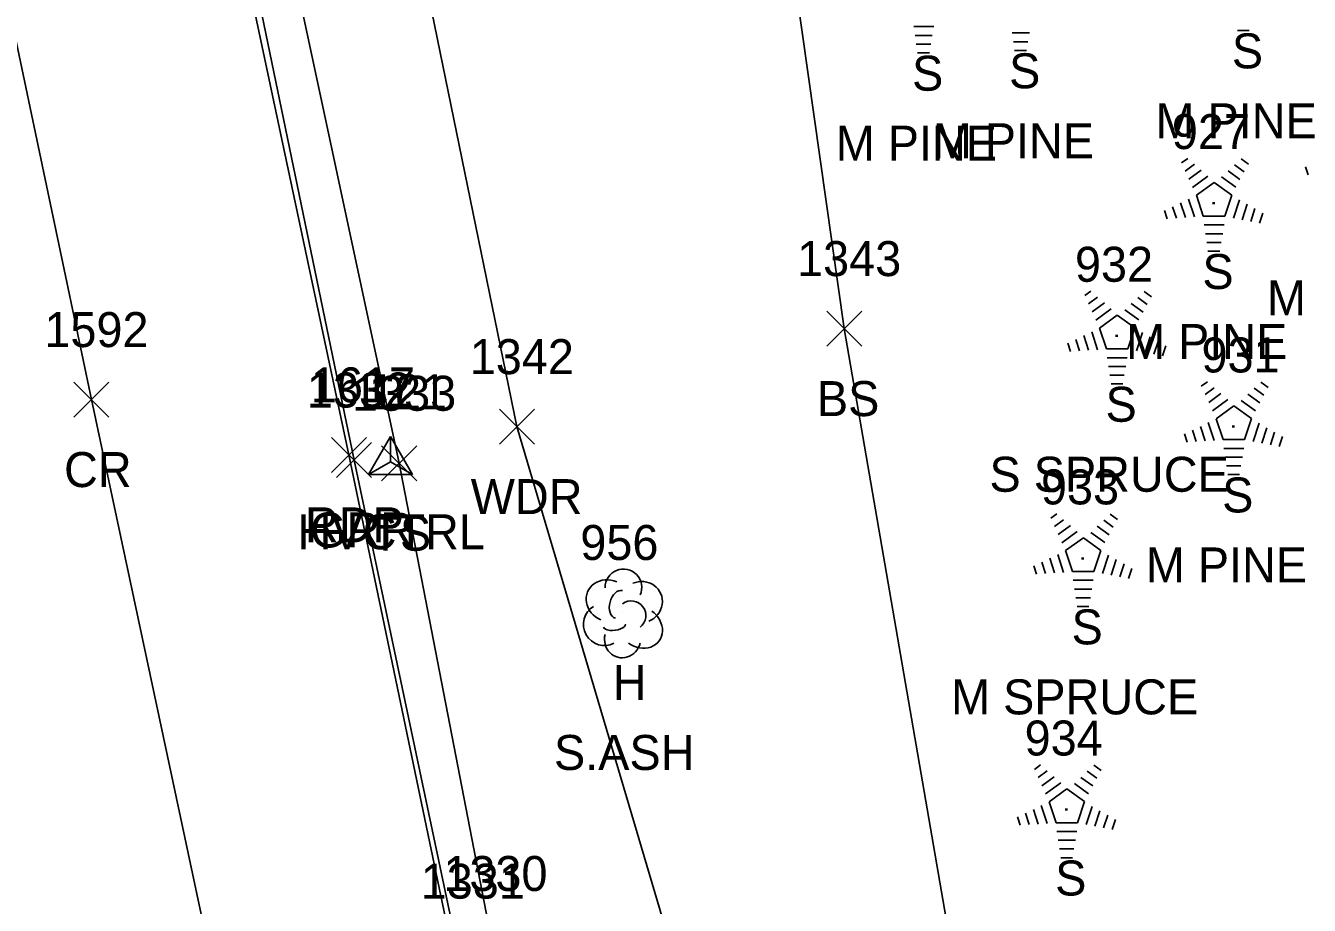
# Model space of a CAD drawing. Extents: x 1545627 to 1546562, y 571176 to 576667.
# Drawn here: x 1546058 to 1546131.4, y 572393.7 to 572443.9 of the extents above; entities that cross this region are included whole.
import ezdxf

# ---------------------------------------------------------------- set-up
doc = ezdxf.new("R2010")
doc.units = 0
for name, color, linetype in [('C_A', 7, 'Continuous'), ('C_I', 7, 'Continuous'), ('CPSM', 7, 'Continuous'), ('L_A', 7, 'Continuous'), ('L_C', 7, 'Continuous'), ('L_I', 7, 'Continuous'), ('L_TIC', 7, 'Continuous'), ('LAWA', 7, 'Continuous'), ('LELB', 7, 'Continuous'), ('LTC', 7, 'Continuous'), ('LTD', 7, 'Continuous'), ('P_A', 7, 'Continuous'), ('P_I', 7, 'Continuous'), ('P_TIC', 7, 'Continuous'), ('PET', 7, 'Continuous'), ('PRC', 7, 'Continuous'), ('R_A', 7, 'Continuous'), ('R_I', 7, 'Continuous'), ('R_TIC', 7, 'Continuous'), ('RGR', 7, 'Continuous')]:
    doc.layers.add(name, color=color, linetype=linetype)

msp = doc.modelspace()

# ---------------------------------------------------------------- linework, layer by layer
at = {"layer": 'CPSM'}
for p, q in [((1546077.639, 572418.298), (1546078.889, 572420.463)), ((1546080.139, 572418.298), (1546078.889, 572420.463)), ((1546078.89, 572419.019), (1546078.889, 572420.463)), ((1546077.639, 572418.298), (1546078.89, 572419.019)), ((1546078.89, 572419.019), (1546078.89, 572419.019)), ((1546078.89, 572419.019), (1546080.139, 572418.298)), ((1546077.639, 572418.298), (1546080.139, 572418.298))]:
    msp.add_line(p, q, dxfattribs=at)
at = {"layer": 'L_TIC'}
for points in [[(1546103.81, 572425.631), (1546105.81, 572427.631)], [(1546105.81, 572425.631), (1546103.81, 572427.631)], [(1546085.111, 572420.028), (1546087.111, 572422.028)], [(1546087.111, 572420.028), (1546085.111, 572422.028)], [(1546078.385, 572417.936), (1546080.385, 572419.936)], [(1546080.385, 572417.936), (1546078.385, 572419.936)]]:
    msp.add_lwpolyline(points, dxfattribs=at)
at = {"layer": 'LAWA'}
msp.add_lwpolyline([(1546132.696, 572194.892), (1546123.453, 572251.154), (1546111.937, 572304.897), (1546099.961, 572374.277), (1546086.111, 572421.028), (1546079.849, 572451.625), (1546071.905, 572496.172), (1546064.394, 572527.582), (1546058.594, 572548.653), (1546052.091, 572585.928), (1546038.425, 572619.665), (1546027.83, 572654.921), (1546018.77, 572685.669), (1546005.342, 572728.46), (1545993.814, 572765.207), (1545980.931, 572799.992)], dxfattribs=at)
at = {"layer": 'LELB'}
for points in [[(1546125.533, 572192.436), (1546119.789, 572223.125), (1546112.539, 572267.479), (1546101.484, 572308.512), (1546092.302, 572354.824), (1546084.689, 572391.492), (1546079.385, 572418.936), (1546072.143, 572452.753), (1546063.265, 572495.373), (1546056.178, 572525.93), (1546052.452, 572548.057), (1546043.75, 572580.7), (1546033.096, 572617.265), (1546022.592, 572652.847), (1546012.21, 572685.195), (1545999.024, 572724.088), (1545985.45, 572763.438), (1545973.138, 572794.948)], [(1546138.092, 572206.647), (1546133.659, 572247.148), (1546122.485, 572312.188), (1546113.316, 572377.356), (1546104.81, 572426.631), (1546099.996, 572460.654), (1546092.988, 572497.654), (1546081.836, 572529.538), (1546071.729, 572550.604), (1546058.937, 572584.302), (1546058.009, 572591.614), (1546041.849, 572621.011), (1546036.285, 572644.955)]]:
    msp.add_lwpolyline(points, dxfattribs=at)
at = {"layer": 'LTC'}
for p, q in [((1546109.929, 572443.89), (1546108.784, 572443.89)), ((1546109.845, 572443.39), (1546108.857, 572443.39)), ((1546115.389, 572443.526), (1546114.401, 572443.526)), ((1546127.949, 572443.667), (1546127.274, 572443.667)), ((1546109.761, 572442.89), (1546108.93, 572442.89)), ((1546115.305, 572443.026), (1546114.474, 572443.026)), ((1546115.222, 572442.526), (1546114.547, 572442.526)), ((1546109.678, 572442.39), (1546109.003, 572442.39)), ((1546124.086, 572436.101), (1546124.44, 572436.358)), ((1546124.295, 572435.635), (1546124.824, 572436.02)), ((1546127.113, 572435.993), (1546127.662, 572435.594)), ((1546127.484, 572436.341), (1546127.903, 572436.037)), ((1546124.505, 572435.17), (1546125.208, 572435.681)), ((1546124.714, 572434.704), (1546125.593, 572435.342)), ((1546126.371, 572435.296), (1546127.18, 572434.708)), ((1546126.742, 572435.645), (1546127.421, 572435.151)), ((1546131.166, 572435.883), (1546131.319, 572435.415)), ((1546124.939, 572434.249), (1546125.951, 572434.983)), ((1546125.951, 572434.983), (1546126.948, 572434.258)), ((1546124.029, 572433.813), (1546124.3, 572432.978)), ((1546124.484, 572434.03), (1546124.815, 572433.01)), ((1546124.939, 572434.249), (1546125.326, 572433.055)), ((1546126.948, 572434.258), (1546126.556, 572433.055)), ((1546127.385, 572433.988), (1546127.047, 572432.948)), ((1546127.83, 572433.737), (1546127.542, 572432.853)), ((1546123.118, 572433.38), (1546123.27, 572432.912)), ((1546123.573, 572433.597), (1546123.785, 572432.945)), ((1546126.556, 572433.055), (1546125.326, 572433.055)), ((1546128.274, 572433.487), (1546128.037, 572432.758)), ((1546128.718, 572433.237), (1546128.532, 572432.663)), ((1546126.518, 572432.555), (1546125.373, 572432.555)), ((1546126.434, 572432.055), (1546125.446, 572432.055)), ((1546126.351, 572431.555), (1546125.519, 572431.555)), ((1546126.267, 572431.055), (1546125.592, 572431.055)), ((1546118.549, 572428.516), (1546118.904, 572428.773)), ((1546121.948, 572428.756), (1546122.367, 572428.452)), ((1546118.759, 572428.05), (1546119.288, 572428.435)), ((1546118.968, 572427.585), (1546119.672, 572428.096)), ((1546121.206, 572428.06), (1546121.885, 572427.566)), ((1546121.576, 572428.408), (1546122.126, 572428.009)), ((1546119.178, 572427.119), (1546120.056, 572427.757)), ((1546119.403, 572426.664), (1546120.414, 572427.398)), ((1546120.414, 572427.398), (1546121.411, 572426.673)), ((1546120.834, 572427.711), (1546121.644, 572427.123)), ((1546118.948, 572426.445), (1546119.279, 572425.425)), ((1546119.403, 572426.664), (1546119.79, 572425.47)), ((1546121.411, 572426.673), (1546121.02, 572425.47)), ((1546121.849, 572426.403), (1546121.511, 572425.363)), ((1546117.582, 572425.795), (1546117.734, 572425.327)), ((1546118.037, 572426.012), (1546118.249, 572425.36)), ((1546118.493, 572426.228), (1546118.764, 572425.393)), ((1546122.293, 572426.152), (1546122.006, 572425.268)), ((1546122.738, 572425.902), (1546122.501, 572425.173)), ((1546121.02, 572425.47), (1546119.79, 572425.47)), ((1546120.982, 572424.97), (1546119.837, 572424.97)), ((1546123.182, 572425.652), (1546122.996, 572425.078)), ((1546120.898, 572424.47), (1546119.91, 572424.47)), ((1546120.814, 572423.97), (1546119.983, 572423.97)), ((1546120.731, 572423.47), (1546120.056, 572423.47)), ((1546125.213, 572423.333), (1546125.568, 572423.591)), ((1546128.612, 572423.574), (1546129.031, 572423.269)), ((1546125.423, 572422.868), (1546125.952, 572423.252)), ((1546125.633, 572422.402), (1546126.336, 572422.913)), ((1546127.87, 572422.877), (1546128.549, 572422.383)), ((1546128.241, 572423.225), (1546128.79, 572422.826)), ((1546125.842, 572421.936), (1546126.721, 572422.574)), ((1546126.067, 572421.481), (1546127.078, 572422.216)), ((1546127.078, 572422.216), (1546128.076, 572421.491)), ((1546127.498, 572422.529), (1546128.308, 572421.94)), ((1546125.612, 572421.262), (1546125.943, 572420.243)), ((1546126.067, 572421.481), (1546126.454, 572420.288)), ((1546128.076, 572421.491), (1546127.684, 572420.288)), ((1546124.246, 572420.612), (1546124.398, 572420.144)), ((1546124.701, 572420.829), (1546124.913, 572420.177)), ((1546125.157, 572421.046), (1546125.428, 572420.21)), ((1546128.513, 572421.22), (1546128.175, 572420.18)), ((1546128.958, 572420.969), (1546128.67, 572420.085)), ((1546129.402, 572420.719), (1546129.165, 572419.99)), ((1546127.684, 572420.288), (1546126.454, 572420.288)), ((1546129.846, 572420.469), (1546129.66, 572419.895)), ((1546127.646, 572419.788), (1546126.501, 572419.788)), ((1546127.562, 572419.288), (1546126.574, 572419.288)), ((1546127.478, 572418.788), (1546126.647, 572418.788)), ((1546127.395, 572418.288), (1546126.72, 572418.288)), ((1546116.608, 572415.793), (1546116.963, 572416.05)), ((1546116.818, 572415.327), (1546117.347, 572415.712)), ((1546119.635, 572415.685), (1546120.185, 572415.286)), ((1546120.006, 572416.033), (1546120.426, 572415.729)), ((1546117.027, 572414.862), (1546117.731, 572415.373)), ((1546117.237, 572414.396), (1546118.115, 572415.034)), ((1546117.461, 572413.941), (1546118.473, 572414.675)), ((1546118.473, 572414.675), (1546119.47, 572413.95)), ((1546118.893, 572414.988), (1546119.703, 572414.4)), ((1546119.264, 572415.337), (1546119.944, 572414.843)), ((1546117.461, 572413.941), (1546117.849, 572412.747)), ((1546119.47, 572413.95), (1546119.079, 572412.747)), ((1546116.096, 572413.289), (1546116.308, 572412.637)), ((1546116.551, 572413.505), (1546116.823, 572412.67)), ((1546117.007, 572413.722), (1546117.338, 572412.702)), ((1546119.908, 572413.68), (1546119.57, 572412.64)), ((1546120.352, 572413.429), (1546120.065, 572412.545)), ((1546115.641, 572413.072), (1546115.793, 572412.604)), ((1546119.079, 572412.747), (1546117.849, 572412.747)), ((1546120.797, 572413.179), (1546120.56, 572412.45)), ((1546121.241, 572412.929), (1546121.054, 572412.355)), ((1546119.041, 572412.247), (1546117.896, 572412.247)), ((1546118.957, 572411.747), (1546117.969, 572411.747)), ((1546118.873, 572411.247), (1546118.041, 572411.247)), ((1546118.789, 572410.747), (1546118.114, 572410.747)), ((1546115.673, 572401.442), (1546116.028, 572401.699)), ((1546119.072, 572401.682), (1546119.491, 572401.377)), ((1546115.883, 572400.976), (1546116.412, 572401.36)), ((1546116.093, 572400.51), (1546116.796, 572401.022)), ((1546118.33, 572400.985), (1546119.009, 572400.492)), ((1546118.7, 572401.334), (1546119.25, 572400.934)), ((1546116.302, 572400.044), (1546117.18, 572400.682)), ((1546116.527, 572399.589), (1546117.538, 572400.324)), ((1546117.538, 572400.324), (1546118.535, 572399.599)), ((1546117.958, 572400.637), (1546118.768, 572400.048)), ((1546116.072, 572399.37), (1546116.403, 572398.351)), ((1546116.527, 572399.589), (1546116.914, 572398.396)), ((1546118.535, 572399.599), (1546118.144, 572398.396)), ((1546118.973, 572399.328), (1546118.635, 572398.289)), ((1546114.706, 572398.721), (1546114.858, 572398.253)), ((1546115.161, 572398.937), (1546115.373, 572398.286)), ((1546115.617, 572399.154), (1546115.888, 572398.319)), ((1546119.418, 572399.078), (1546119.13, 572398.193)), ((1546119.862, 572398.828), (1546119.625, 572398.098)), ((1546120.306, 572398.577), (1546120.12, 572398.003)), ((1546118.144, 572398.396), (1546116.914, 572398.396)), ((1546118.106, 572397.896), (1546116.961, 572397.896)), ((1546118.022, 572397.396), (1546117.034, 572397.396)), ((1546117.938, 572396.896), (1546117.107, 572396.896)), ((1546117.855, 572396.396), (1546117.18, 572396.396))]:
    msp.add_line(p, q, dxfattribs=at)
at = {"layer": 'LTD'}
msp.add_line((1546092.151, 572410.408), (1546092.151, 572410.408), dxfattribs=at)
msp.add_line((1546092.151, 572410.408), (1546092.151, 572410.408), dxfattribs=at)
msp.add_arc((1546092.198, 572411.842), 1.047, 335.52715, 180.95627, dxfattribs=at)
for centre, major_axis, ratio, start_param, end_param in [((1546091.359, 572411.075), (1.21, -0.512), 0.895232, 1.570796, 4.712389), ((1546091.943, 572410.866), (-0.208, -0.792), 0.645439, 3.141593, 6.283185), ((1546093.193, 572410.992), (-1.141, -0.483), 0.949671, 1.570796, 4.712389), ((1546092.651, 572410.242), (-0.5, 0.667), 0.989748, 3.141593, 6.283185), ((1546091.068, 572409.7), (0.584, -1.042), 0.959034, 3.141593, 6.283185), ((1546093.151, 572409.575), (-1.09, 0.792), 0.841452, 1.570796, 4.712389), ((1546091.693, 572409.658), (-0.625, -0.083), 0.423636, 0, 3.141593), ((1546092.151, 572408.908), (0.265, 1.061), 0.942809, 1.570796, 4.712389)]:
    msp.add_ellipse(centre, major_axis=major_axis, ratio=ratio, start_param=start_param, end_param=end_param, dxfattribs=at)
at = {"layer": 'P_TIC'}
for points in [[(1546060.807, 572421.575), (1546062.807, 572423.575)], [(1546062.807, 572421.575), (1546060.807, 572423.575)], [(1546075.514, 572418.415), (1546077.514, 572420.415)], [(1546077.514, 572418.415), (1546075.514, 572420.415)]]:
    msp.add_lwpolyline(points, dxfattribs=at)
at = {"layer": 'PET'}
msp.add_lwpolyline([(1546019.19, 572549.754), (1546028.198, 572511.711), (1546038.291, 572466.999), (1546043.906, 572438.712), (1546048.458, 572419.826), (1546059.016, 572375.225), (1546068.403, 572327.334), (1546078.966, 572280.941), (1546081.531, 572262.744), (1546083.99, 572253.102), (1546089.432, 572227.88), (1546096.04, 572198.55), (1546104.441, 572159.778), (1546113.192, 572174.919), (1546122.626, 572188.985), (1546117.061, 572219.813), (1546108.582, 572263.735), (1546099.519, 572308.129), (1546091.038, 572348.985), (1546082.958, 572388.468), (1546076.514, 572419.415), (1546067.661, 572461.142), (1546060.504, 572495.348), (1546051.115, 572536.864)], dxfattribs=at)
at = {"layer": 'PRC'}
msp.add_lwpolyline([(1545789.966, 573149.912), (1545812.745, 573103.838), (1545835.714, 573057.35), (1545858.015, 573011.302), (1545880.297, 572964.263), (1545901.328, 572918.696), (1545921.742, 572873.141), (1545941.501, 572826.683), (1545959.258, 572783.141), (1545976.305, 572737.153), (1545992.657, 572690.864), (1546006.775, 572646.349), (1546020.379, 572601.275), (1546032.774, 572553.215), (1546041.68, 572514.934), (1546051.794, 572470.298), (1546061.807, 572422.575), (1546071.322, 572377.997), (1546081.349, 572330.367), (1546091.011, 572283.405), (1546102.063, 572230.003), (1546107.883, 572201.699), (1546113.192, 572174.919)], dxfattribs=at)
at = {"layer": 'R_TIC'}
for points in [[(1546075.806, 572418.122), (1546077.806, 572420.122)], [(1546077.806, 572418.122), (1546075.806, 572420.122)]]:
    msp.add_lwpolyline(points, dxfattribs=at)
at = {"layer": 'RGR'}
msp.add_lwpolyline([(1546122.896, 572190.91), (1546117.322, 572223.344), (1546108.745, 572265.603), (1546099.878, 572308.896), (1546090.289, 572354.448), (1546082.741, 572391.052), (1546076.806, 572419.122), (1546069.968, 572452.166), (1546060.892, 572495.215), (1546054.251, 572525.612), (1546048.911, 572547.317), (1546040.705, 572580.212), (1546030.582, 572616.088), (1546020.216, 572652.04), (1546009.859, 572685.101), (1545996.97, 572723.718), (1545983.077, 572762.484), (1545970.878, 572794.287)], dxfattribs=at)

# ---------------------------------------------------------------- texts
at = {"layer": 'C_A'}
msp.add_text('HVCTRL', height=2, dxfattribs=at).set_placement((1546073.582, 572414.019))
at = {"layer": 'C_I'}
msp.add_text('121', height=2, dxfattribs=at).set_placement((1546077.661, 572422.019))
at = {"layer": 'L_A'}
for s, p in [('S', (1546126.958, 572441.504)), ('S', (1546108.687, 572440.227)), ('S', (1546114.231, 572440.363)), ('S', (1546125.276, 572428.893)), ('BS', (1546103.251, 572421.631)), ('S', (1546119.74, 572421.308)), ('WDR', (1546083.473, 572416.028)), ('S', (1546126.404, 572416.125)), ('TS', (1546077.795, 572413.936)), ('S', (1546117.799, 572408.585)), ('H', (1546091.584, 572405.408)), ('S', (1546116.864, 572394.233))]:
    msp.add_text(s, height=2, dxfattribs=at).set_placement(p)
at = {"layer": 'L_C'}
for s, p in [('M PINE', (1546122.596, 572437.504)), ('M PINE', (1546104.325, 572436.227)), ('M PINE', (1546109.869, 572436.363)), ('M PINE', (1546128.962, 572427.396)), ('M PINE', (1546120.914, 572424.893)), ('S SPRUCE', (1546113.11, 572417.308)), ('M PINE', (1546122.042, 572412.125)), ('M SPRUCE', (1546110.917, 572404.585)), ('S.ASH', (1546088.23, 572401.408))]:
    msp.add_text(s, height=2, dxfattribs=at).set_placement(p)
at = {"layer": 'L_I'}
for s, p in [('927', (1546123.528, 572436.893)), ('1343', (1546102.117, 572429.631)), ('932', (1546117.992, 572429.308)), ('1342', (1546083.418, 572424.028)), ('931', (1546125.223, 572424.125)), ('1333', (1546076.693, 572421.936)), ('933', (1546116.051, 572416.585)), ('956', (1546089.734, 572413.408)), ('934', (1546115.116, 572402.233)), ('1330', (1546081.909, 572394.492))]:
    msp.add_text(s, height=2, dxfattribs=at).set_placement(p)
at = {"layer": 'LTC'}
for p in [(1546125.833, 572433.997), (1546120.297, 572426.412), (1546126.961, 572421.229), (1546118.356, 572413.689), (1546117.421, 572399.337)]:
    msp.add_text('.', height=1.037, rotation=270, dxfattribs=at).set_placement(p)
at = {"layer": 'P_A'}
for s, p in [('CR', (1546060.24, 572417.575)), ('RDP', (1546074.003, 572414.415))]:
    msp.add_text(s, height=2, dxfattribs=at).set_placement(p)
at = {"layer": 'P_I'}
for s, p in [('1592', (1546059.114, 572425.575)), ('1617', (1546074.341, 572422.415))]:
    msp.add_text(s, height=2, dxfattribs=at).set_placement(p)
at = {"layer": 'R_A'}
msp.add_text('GRR', height=2, dxfattribs=at).set_placement((1546074.294, 572414.122))
at = {"layer": 'R_I'}
for s, p in [('1332', (1546074.113, 572422.122)), ('1331', (1546080.615, 572394.052))]:
    msp.add_text(s, height=2, dxfattribs=at).set_placement(p)

doc.saveas('drawing.dxf')
